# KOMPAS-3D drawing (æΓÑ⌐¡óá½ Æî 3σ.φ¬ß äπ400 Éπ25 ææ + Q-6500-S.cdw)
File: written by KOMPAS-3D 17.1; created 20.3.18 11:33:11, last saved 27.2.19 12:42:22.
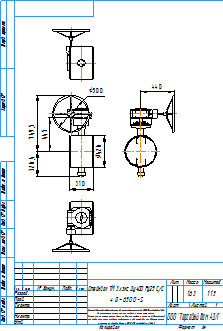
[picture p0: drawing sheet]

Sheet 1: A4, portrait

Title block, sheet 1: name: Стейнвал ТМ 3х.экс Ду400 Ру25 С/С / + Q-6500-S; mass: 163; sheets: 1; sheet format: A4; stored path: C:\Users\kka\KOMPAS_Work\Дисковые повортные затворы ф. Boteli\Стейнвал + редуктор-привода\Стейнвал ТМ 3х.экс Ду400 Ру25 СС + Q-6500-S.cdw

Views: Вид 1, Проекционный вид 3, Проекционный вид 4
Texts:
  kka
  adl
  Рама для чертежей
  Лит-Масса-Масштаб
  Материал-Предприятие
  Масштаб
  Изм.
  Лист
  № докум.
  Подп.
  Дата
  Лит.
  Разраб.
  Пров.
  Т.контр.
  Листов
  Внимание! Данный продукт является объектом авторского права ООО «Торговый Дом АДЛ».
  Запрещается изменение, копирование, распространение
  (в том числе путем копирования на другие сайты и ресурсы в Интернете)
  или любое иное использование информации и объектов без предварительного
  согласия правообладателя (ООО «Торговый Дом АДЛ»).
  Н.контр.
  Утв.
  ООО "Торговый дом АДЛ"
  Изменение
  Номер документа
  Подпись
  Обозначение документа
  Наименование изделия
  Масса изделия по ГОСТ 2.109-73
  Порядковый номер листа
  Общее количество листов в документе
  Характер работы, выполненной лицом, подписавшим документ
  Наименование или индекс предприятия, выпускающего документ
  Инв. № подл.
  Подп. и дата
  Взам. инв. №
  Инв. № дубл.
  Инвентарный номер подлинника по ГОСТ 2.501-68
  Подпись принявшего подлинник в отдел технической документации
  Инвентарный номер подлинника, взамен которого выпущен данный подлинник
  Инвентарный номер дубликата по ГОСТ 2.502-68
  Подпись принявшего дубликат в отдел технической документации
  Справ. №
  Перв. примен.
  Обозначение документа, взамен или на основании которого выпущен данный документ
  Обозначение документа, в котором впервые записан данный документ
  Подпись лица, копировавшего чертеж
  Обозначение формата листа
  !Рама для чертежа
Dimensions and other numbers on the sheet: 500; 310; 326,4; 749,5; 426; 445; 1:15; 1; 163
